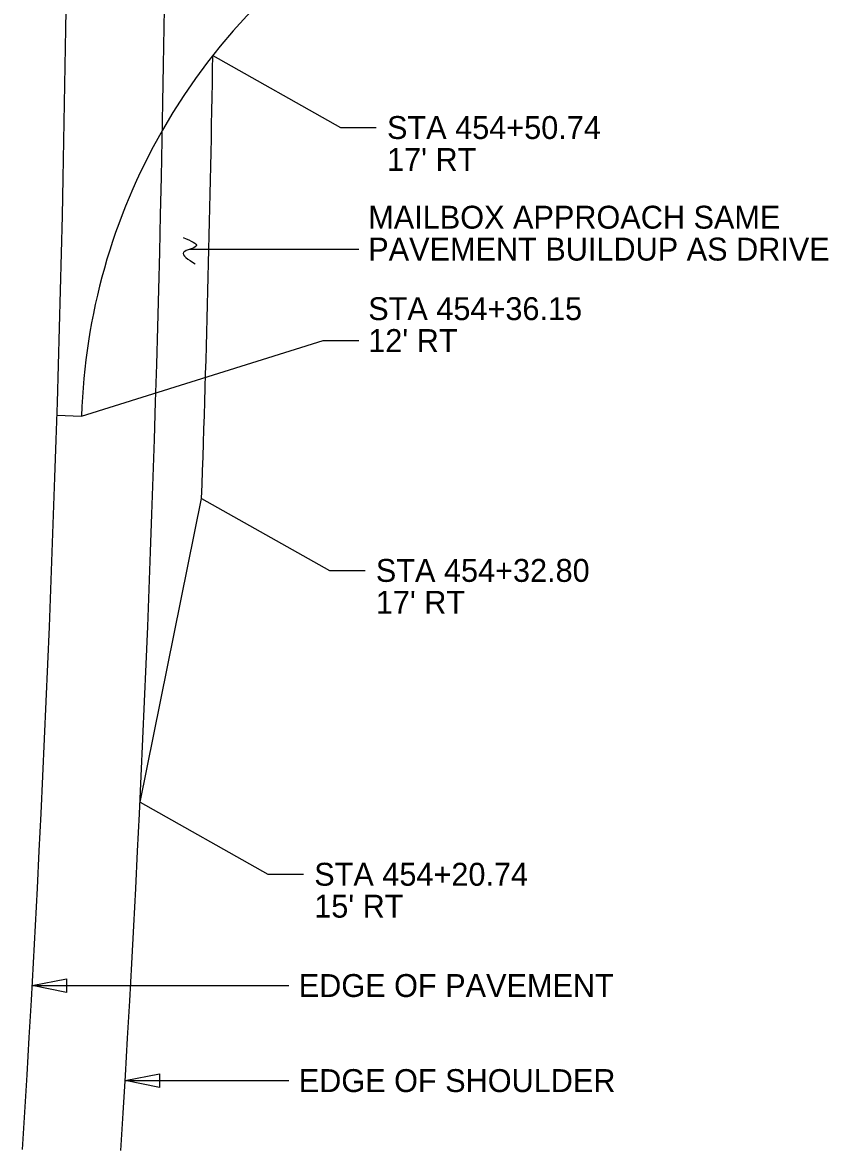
# Model space of a CAD drawing. Extents: x 0 to 3518, y -260 to 220.
# Drawn here: x 71.6 to 120.8, y -169.5 to -100.5 of the extents above; entities that cross this region are included whole.
import ezdxf

# ---------------------------------------------------------------- set-up
doc = ezdxf.new("R2010")
doc.units = 0
for name, color, linetype in [('GE_P_Alignment_100_Stations', 7, 'Continuous'), ('MT_P_Temp_Road', 7, 'Continuous'), ('PF_P_Grade_Line', 7, 'Continuous'), ('SC_Scratch2', 7, 'Continuous'), ('TX_P_1', 7, 'Continuous')]:
    doc.layers.add(name, color=color, linetype=linetype)

msp = doc.modelspace()

# ---------------------------------------------------------------- linework, layer by layer
at = {"layer": 'GE_P_Alignment_100_Stations'}
msp.add_arc((-1374.57, -79.243), 1449, 356.43222, 2.216217, dxfattribs=at)
at = {"layer": 'MT_P_Temp_Road'}
for p, q in [((73.722, -124.524), (75.222, -124.571)), ((78.796, -148.181), (82.56, -129.61))]:
    msp.add_line(p, q, dxfattribs=at)
for centre, radius, start, end in [((112.703, -125.743), 37.5, 90, 150.19642), ((-1374.57, -79.243), 1458, 358.020322, 359.084459), ((112.703, -125.743), 37.5, 150.19642, 178.20922)]:
    msp.add_arc(centre, radius, start, end, dxfattribs=at)
at = {"layer": 'PF_P_Grade_Line'}
msp.add_arc((-1374.57, -79.243), 1455, 356.445051, 2.216217, dxfattribs=at)
at = {"layer": 'SC_Scratch2'}
for points in [[(74.312, -158.962), (74.312, -159.802), (72.212, -159.382)], [(79.989, -164.772), (79.989, -165.612), (77.889, -165.192)]]:
    msp.add_lwpolyline(points, close=True, dxfattribs=at)
at = {"layer": 'TX_P_1'}
for p, q in [((83.244, -102.54), (91.051, -106.939)), ((91.051, -106.939), (93.232, -106.939)), ((81.824, -114.37), (92.162, -114.37)), ((75.222, -124.571), (89.982, -119.96)), ((89.982, -119.96), (92.162, -119.96)), ((82.56, -129.61), (90.367, -134.009)), ((90.367, -134.009), (92.548, -134.009)), ((78.796, -148.181), (86.603, -152.581)), ((86.603, -152.581), (88.784, -152.581)), ((72.212, -159.382), (87.884, -159.382)), ((77.889, -165.192), (87.884, -165.192))]:
    msp.add_line(p, q, dxfattribs=at)
msp.add_spline([(81.44, -113.664), (82.231, -114.192), (81.462, -114.566), (82.165, -115.27)], degree=3, dxfattribs=at)

# ---------------------------------------------------------------- texts
for s, p in [('STA 454+50.74', (93.886, -107.639)), ("17' RT", (93.886, -109.59)), ('MAILBOX APPROACH SAME', (92.738, -113.119)), ('PAVEMENT BUILDUP AS DRIVE', (92.738, -115.07)), ('STA 454+36.15', (92.738, -118.709)), ("12' RT", (92.738, -120.66)), ('STA 454+32.80', (93.202, -134.709)), ("17' RT", (93.202, -136.66)), ('STA 454+20.74', (89.438, -153.281)), ("15' RT", (89.438, -155.232)), ('EDGE OF PAVEMENT', (88.492, -160.082)), ('EDGE OF SHOULDER', (88.492, -165.892))]:
    msp.add_text(s, height=1.4, dxfattribs=at).set_placement(p)

doc.saveas('drawing.dxf')
